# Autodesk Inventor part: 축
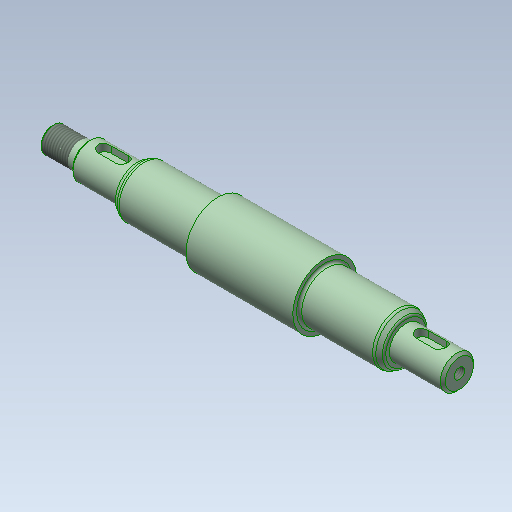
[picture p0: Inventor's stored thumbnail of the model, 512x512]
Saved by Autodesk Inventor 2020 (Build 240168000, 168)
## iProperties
Created: 2024-02
Part Number: 축
Material: 강철, 탄소
Document SubType Name: Modeling
Designer: mdu-01
Density: 1 g/cm^3
Appearance: 기본값(1)
Author: mdu-01
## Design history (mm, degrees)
sketch "스케치1"
  geometry: L1 (0, 0)-(160, 0); L2 (0, 0)-(0, -5); L3 (0, -5)-(14, -5); L4 (14, -5)-(14, -6); L5 (15, -7)-(33, -7); L6 (33, -7)-(33, -7.923); L7 (36.134, -10)-(64, -10); L8 (65, -11)-(65, -12.5); L9 (65, -12.5)-(107, -12.5); L10 (107, -12.5)-(107, -11); L11 (108, -10)-(135.866, -10); L12 (139, -7.923)-(139, -6.5); L13 (139, -6.5)-(159, -6.5); L14 (160, -5.5)-(160, 0); L15 (159, -6.5)-(160, -5.5); L16 (14, -6)-(15, -7); L17 (33.5, -8.789)-(35.134, -9.732); L18 (138.5, -8.789)-(136.866, -9.732); L19 (18, 7)-(30, 7); L20 (30, 7)-(30, 4); L21 (30, 4)-(18, 4); L22 (18, 4)-(18, 7); L23 (143, 6.5)-(155, 6.5); L24 (155, 6.5)-(155, 3.5); L25 (155, 3.5)-(143, 3.5); L26 (143, 3.5)-(143, 6.5); A1 r 1 centre (64, -11) between (65, -11) and (64, -10); A2 r 1 centre (108, -11) between (108, -10) and (107, -11); A3 r 1 centre (34, -7.923) between (33, -7.923) and (33.5, -8.789); A4 r 1 centre (138, -7.923) between (138.5, -8.789) and (139, -7.923); A5 r 2 centre (135.866, -8) between (135.866, -10) and (136.866, -9.732); A6 r 2 centre (36.134, -8) between (35.134, -9.732) and (36.134, -10); 4 further points
  constraints: 52 end point, 15 parallel, 12 point on circle, 12 tangent, 8 point on line, 6 centre point, 4 perpendicular, 3 equal radius, 3 horizontal, 1 collinear
  dimensions: "d0" = 160 distance of L1.start L1.end; "d1" = 14 distance between parallel lines of L4 L2; "d2" = 33 distance between parallel lines of L6 L2; "d3" = 65 distance between parallel lines of L8 L2; "d4" = 21 distance between parallel lines of L12 L14; "d5" = 53 distance between parallel lines of L10 L14; "d6" = 10 diameter of L3 L1; "d7" = 14 diameter of L5 L1; "d8" = 20 diameter of L7 L1; "d9" = 13 diameter of L13 L1; "d10" = 25 diameter of L9 L1; "d11" = 1 radius of A1; "d12" = 1 distance of L13.end point (160, -6.5); "d13" = 1 distance of L14.start point (160, -6.5) (= d12); "d14" = 1 distance of L4.end point (14, -7) (= d12); "d15" = 1 distance of L5.start point (14, -7) (= d14); "d16" = 17 diameter of point (139, -8.5) L1; "d17" = 30 deg angle of L11 L18; "d18" = 17 diameter of point (33, -8.5) L1; "d19" = 30 deg angle of L7 L17; "d20" = 1 radius of A3; "d21" = 2 radius of A5; "d22" = 3 distance between parallel lines of L21 L19; "d23" = 12 distance between parallel lines of L20 L22; "d24" = 3 distance between parallel lines of L20 L6; "d25" = 14 diameter of L19 L1; "d26" = 3 distance between parallel lines of L25 L23; "d27" = 12 distance between parallel lines of L24 L26; "d28" = 4 distance between parallel lines of L26 L12; "d29" = 13 diameter of L23 L1
revolve "회전1" stored, may be unused: angle "d30" = 90 deg
extrude "돌출1" cut sketch "스케치1" stored distance "d31" = 5; taper "d32" = 0 deg
fillet "모깎기1" dims "d33" = 2.5
feature "스레드1" dims "d34" = 11, "d35" = 0
chamfer "모따기1" distance "d36" = 0.541; stored, may be unused: second distance "d37" = 2, angle "d38" = 45 deg
hole "구멍1" diameter "d41" = 4.134; stored, may be unused: countersink angle "d45" = 90 deg, drill point angle "d47" = 118 deg; dims "d39" = 10, "d40" = 10, "d42" = 10, "d43" = 4, "d44" = 2, "d46" = 12
node "솔리드1"
